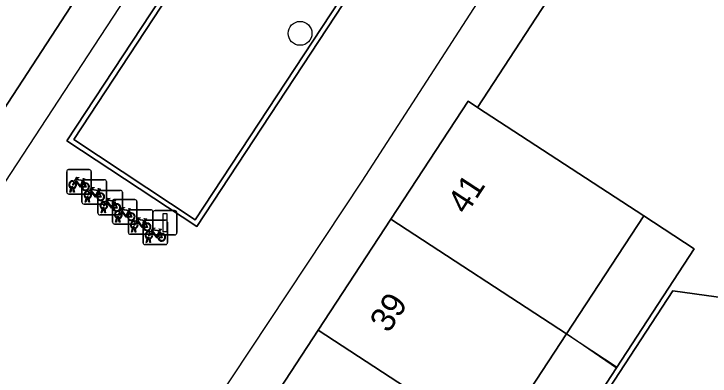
# Model space of a CAD drawing. Extents: x 155640 to 156811, y 382821 to 384049.
# Drawn here: x 156456.82 to 156485.33, y 383747.46 to 383762.3 of the extents above; entities that cross this region are included whole.
import ezdxf

# ---------------------------------------------------------------- set-up
doc = ezdxf.new("R2010")
doc.units = 0
for name, color, linetype in [('IMGEO_Boom', 7, 'Continuous'), ('IMGEO_Fietsenrek', 7, 'Continuous'), ('IMGEO_Lichtmast', 7, 'Continuous'), ('IMGEO_Lijnafwatering', 7, 'Continuous'), ('IMGEO_Muur', 7, 'Continuous'), ('IMGEO_Pand', 7, 'Continuous'), ('IMGEO_Pand_nummerreeks', 7, 'Continuous'), ('IMGEO_Pand_overbouw', 7, 'Continuous'), ('IMGEO_Rijbaan_lokaal_gesloten', 7, 'Continuous'), ('IMGEO_Voetgangersgebied_open', 7, 'Continuous'), ('IMGEO_Voetpad_open', 7, 'Continuous')]:
    doc.layers.add(name, color=color, linetype=linetype)

msp = doc.modelspace()

# ---------------------------------------------------------------- linework, layer by layer
at = {"layer": 'IMGEO_Boom'}
msp.add_circle((156468.536, 383761.508), 0.489, dxfattribs=at)
at = {"layer": 'IMGEO_Fietsenrek'}
for p, q in [((156458.983, 383754.998), (156458.983, 383755.839)), ((156458.983, 383755.839), (156458.983, 383754.998)), ((156459.058, 383755.923), (156459.899, 383755.923)), ((156459.899, 383755.923), (156459.058, 383755.923)), ((156459.983, 383755.848), (156459.983, 383755.007)), ((156459.983, 383755.007), (156459.983, 383755.848)), ((156459.605, 383754.587), (156459.605, 383755.428)), ((156459.605, 383755.428), (156459.605, 383754.587)), ((156459.67, 383755.472), (156459.706, 383755.377)), ((156459.68, 383755.512), (156460.521, 383755.512)), ((156460.521, 383755.512), (156459.68, 383755.512)), ((156460.605, 383755.437), (156460.605, 383754.596)), ((156460.605, 383754.596), (156460.605, 383755.437)), ((156459.11, 383755.007), (156459.149, 383755.167)), ((156459.179, 383755.155), (156459.144, 383755.007)), ((156459.221, 383755.179), (156459.22, 383755.183)), ((156459.262, 383755.007), (156459.228, 383755.149)), ((156459.252, 383755.19), (156459.253, 383755.183)), ((156459.26, 383755.153), (156459.295, 383755.007)), ((156459.908, 383754.923), (156459.067, 383754.923)), ((156459.067, 383754.923), (156459.908, 383754.923)), ((156459.144, 383755.007), (156459.11, 383755.007)), ((156459.295, 383755.007), (156459.262, 383755.007)), ((156460.26, 383754.144), (156460.26, 383754.985)), ((156460.26, 383754.985), (156460.26, 383754.144)), ((156460.292, 383755.061), (156460.328, 383754.966)), ((156460.335, 383755.069), (156461.176, 383755.069)), ((156461.176, 383755.069), (156460.335, 383755.069)), ((156461.26, 383754.994), (156461.26, 383754.153)), ((156461.26, 383754.153), (156461.26, 383754.994)), ((156459.732, 383754.596), (156459.771, 383754.756)), ((156459.766, 383754.596), (156459.732, 383754.596)), ((156459.801, 383754.744), (156459.766, 383754.596)), ((156459.843, 383754.768), (156459.842, 383754.772)), ((156459.884, 383754.596), (156459.85, 383754.738)), ((156459.874, 383754.779), (156459.875, 383754.772)), ((156459.882, 383754.742), (156459.917, 383754.596)), ((156459.917, 383754.596), (156459.884, 383754.596)), ((156460.856, 383753.769), (156460.856, 383754.61)), ((156460.856, 383754.61), (156460.856, 383753.769)), ((156460.931, 383754.694), (156461.772, 383754.694)), ((156461.772, 383754.694), (156460.931, 383754.694)), ((156460.947, 383754.618), (156460.983, 383754.523)), ((156461.856, 383754.619), (156461.856, 383753.778)), ((156461.856, 383753.778), (156461.856, 383754.619)), ((156460.53, 383754.512), (156459.689, 383754.512)), ((156459.689, 383754.512), (156460.53, 383754.512)), ((156460.387, 383754.153), (156460.426, 383754.313)), ((156460.456, 383754.301), (156460.421, 383754.153)), ((156460.498, 383754.325), (156460.497, 383754.329)), ((156460.539, 383754.153), (156460.505, 383754.295)), ((156460.529, 383754.336), (156460.53, 383754.329)), ((156460.537, 383754.299), (156460.572, 383754.153)), ((156461.58, 383754.277), (156462.421, 383754.277)), ((156462.421, 383754.277), (156461.58, 383754.277)), ((156461.185, 383754.069), (156460.344, 383754.069)), ((156460.344, 383754.069), (156461.185, 383754.069)), ((156460.421, 383754.153), (156460.387, 383754.153)), ((156460.572, 383754.153), (156460.539, 383754.153)), ((156461.505, 383753.352), (156461.505, 383754.193)), ((156461.505, 383754.193), (156461.505, 383753.352)), ((156461.543, 383754.243), (156461.579, 383754.148)), ((156462.505, 383754.202), (156462.505, 383753.361)), ((156462.505, 383753.361), (156462.505, 383754.202)), ((156460.983, 383753.778), (156461.022, 383753.938)), ((156461.017, 383753.778), (156460.983, 383753.778)), ((156461.052, 383753.926), (156461.017, 383753.778)), ((156461.094, 383753.95), (156461.093, 383753.954)), ((156461.135, 383753.778), (156461.101, 383753.92)), ((156461.125, 383753.961), (156461.126, 383753.954)), ((156461.133, 383753.924), (156461.168, 383753.778)), ((156461.168, 383753.778), (156461.135, 383753.778)), ((156462.106, 383752.928), (156462.106, 383753.769)), ((156462.106, 383753.769), (156462.106, 383752.928)), ((156462.181, 383753.853), (156463.022, 383753.853)), ((156463.022, 383753.853), (156462.181, 383753.853)), ((156462.192, 383753.826), (156462.228, 383753.731)), ((156463.106, 383753.778), (156463.106, 383752.937)), ((156463.106, 383752.937), (156463.106, 383753.778)), ((156461.781, 383753.694), (156460.94, 383753.694)), ((156460.94, 383753.694), (156461.781, 383753.694)), ((156461.632, 383753.361), (156461.671, 383753.521)), ((156461.701, 383753.509), (156461.666, 383753.361)), ((156461.743, 383753.533), (156461.742, 383753.537)), ((156461.784, 383753.361), (156461.75, 383753.503)), ((156461.774, 383753.544), (156461.775, 383753.537)), ((156461.782, 383753.507), (156461.817, 383753.361)), ((156462.43, 383753.277), (156461.589, 383753.277)), ((156461.589, 383753.277), (156462.43, 383753.277)), ((156461.666, 383753.361), (156461.632, 383753.361)), ((156461.817, 383753.361), (156461.784, 383753.361)), ((156462.793, 383753.402), (156462.829, 383753.307)), ((156463.031, 383752.853), (156462.19, 383752.853)), ((156462.19, 383752.853), (156463.031, 383752.853)), ((156462.233, 383752.937), (156462.272, 383753.097)), ((156462.267, 383752.937), (156462.233, 383752.937)), ((156462.302, 383753.085), (156462.267, 383752.937)), ((156462.344, 383753.109), (156462.343, 383753.113)), ((156462.385, 383752.937), (156462.351, 383753.079)), ((156462.375, 383753.12), (156462.376, 383753.113)), ((156462.383, 383753.083), (156462.418, 383752.937)), ((156462.418, 383752.937), (156462.385, 383752.937))]:
    msp.add_line(p, q, dxfattribs=at)
for points in [[(156459.317, 383755.397), (156459.265, 383755.307), (156459.225, 383755.282), (156459.226, 383755.329), (156459.281, 383755.423)], [(156459.296, 383755.449), (156459.391, 383755.613), (156459.477, 383755.599), (156459.479, 383755.59), (156459.423, 383755.579), (156459.396, 383755.534), (156459.652, 383755.493)], [(156459.592, 383755.205), (156459.542, 383755.205), (156459.351, 383755.456), (156459.332, 383755.424)], [(156459.639, 383755.468), (156459.382, 383755.509), (156459.365, 383755.48), (156459.532, 383755.26), (156459.639, 383755.468)], [(156459.687, 383755.37), (156459.657, 383755.447), (156459.548, 383755.229), (156459.591, 383755.229)], [(156459.652, 383755.493), (156459.677, 383755.542), (156459.671, 383755.546), (156459.648, 383755.55), (156459.636, 383755.557), (156459.635, 383755.56), (156459.637, 383755.565), (156459.732, 383755.55), (156459.734, 383755.54), (156459.724, 383755.527), (156459.712, 383755.521), (156459.698, 383755.527), (156459.67, 383755.472)], [(156459.621, 383755.229), (156459.741, 383755.228), (156459.697, 383755.342)], [(156459.717, 383755.349), (156459.772, 383755.204), (156459.622, 383755.204)], [(156459.918, 383755.038), (156460.013, 383755.202), (156460.099, 383755.188), (156460.101, 383755.179), (156460.045, 383755.168), (156460.018, 383755.123), (156460.274, 383755.082)], [(156460.274, 383755.082), (156460.299, 383755.131), (156460.293, 383755.135), (156460.27, 383755.139), (156460.258, 383755.146), (156460.257, 383755.149), (156460.259, 383755.154), (156460.354, 383755.139), (156460.356, 383755.129), (156460.346, 383755.116), (156460.334, 383755.11), (156460.32, 383755.116), (156460.292, 383755.061)], [(156459.939, 383754.986), (156459.887, 383754.896), (156459.847, 383754.871), (156459.848, 383754.918), (156459.903, 383755.012)], [(156460.214, 383754.794), (156460.164, 383754.794), (156459.973, 383755.045), (156459.954, 383755.013)], [(156460.261, 383755.057), (156460.004, 383755.098), (156459.987, 383755.069), (156460.154, 383754.849), (156460.261, 383755.057)], [(156460.309, 383754.959), (156460.279, 383755.036), (156460.17, 383754.818), (156460.213, 383754.818)], [(156460.243, 383754.818), (156460.363, 383754.817), (156460.319, 383754.931)], [(156460.339, 383754.938), (156460.394, 383754.793), (156460.244, 383754.793)], [(156460.594, 383754.543), (156460.542, 383754.453), (156460.502, 383754.428), (156460.503, 383754.475), (156460.558, 383754.569)], [(156460.573, 383754.595), (156460.668, 383754.759), (156460.754, 383754.745), (156460.756, 383754.736), (156460.7, 383754.725), (156460.673, 383754.68), (156460.929, 383754.639)], [(156460.869, 383754.351), (156460.819, 383754.351), (156460.628, 383754.602), (156460.609, 383754.57)], [(156460.916, 383754.614), (156460.659, 383754.655), (156460.642, 383754.626), (156460.809, 383754.406), (156460.916, 383754.614)], [(156460.964, 383754.516), (156460.934, 383754.593), (156460.825, 383754.375), (156460.868, 383754.375)], [(156460.929, 383754.639), (156460.954, 383754.688), (156460.948, 383754.692), (156460.925, 383754.696), (156460.913, 383754.703), (156460.912, 383754.706), (156460.914, 383754.711), (156461.009, 383754.696), (156461.011, 383754.686), (156461.001, 383754.673), (156460.989, 383754.667), (156460.975, 383754.673), (156460.947, 383754.618)], [(156460.898, 383754.375), (156461.018, 383754.374), (156460.974, 383754.488)], [(156460.994, 383754.495), (156461.049, 383754.35), (156460.899, 383754.35)], [(156461.169, 383754.22), (156461.264, 383754.384), (156461.35, 383754.37), (156461.352, 383754.361), (156461.296, 383754.35), (156461.269, 383754.305), (156461.525, 383754.264)], [(156461.512, 383754.239), (156461.255, 383754.28), (156461.238, 383754.251), (156461.405, 383754.031), (156461.512, 383754.239)], [(156461.525, 383754.264), (156461.55, 383754.313), (156461.544, 383754.317), (156461.521, 383754.321), (156461.509, 383754.328), (156461.508, 383754.331), (156461.51, 383754.336), (156461.605, 383754.321), (156461.607, 383754.311), (156461.597, 383754.298), (156461.585, 383754.292), (156461.571, 383754.298), (156461.543, 383754.243)], [(156461.19, 383754.168), (156461.138, 383754.078), (156461.098, 383754.053), (156461.099, 383754.1), (156461.154, 383754.194)], [(156461.465, 383753.976), (156461.415, 383753.976), (156461.224, 383754.227), (156461.205, 383754.195)], [(156461.56, 383754.141), (156461.53, 383754.218), (156461.421, 383754), (156461.464, 383754)], [(156461.494, 383754), (156461.614, 383753.999), (156461.57, 383754.113)], [(156461.59, 383754.12), (156461.645, 383753.975), (156461.495, 383753.975)], [(156461.839, 383753.751), (156461.787, 383753.661), (156461.747, 383753.636), (156461.748, 383753.683), (156461.803, 383753.777)], [(156461.818, 383753.803), (156461.913, 383753.967), (156461.999, 383753.953), (156462.001, 383753.944), (156461.945, 383753.933), (156461.918, 383753.888), (156462.174, 383753.847)], [(156462.114, 383753.559), (156462.064, 383753.559), (156461.873, 383753.81), (156461.854, 383753.778)], [(156462.161, 383753.822), (156461.904, 383753.863), (156461.887, 383753.834), (156462.054, 383753.614), (156462.161, 383753.822)], [(156462.209, 383753.724), (156462.179, 383753.801), (156462.07, 383753.583), (156462.113, 383753.583)], [(156462.239, 383753.703), (156462.294, 383753.558), (156462.144, 383753.558)], [(156462.174, 383753.847), (156462.199, 383753.896), (156462.193, 383753.9), (156462.17, 383753.904), (156462.158, 383753.911), (156462.157, 383753.914), (156462.159, 383753.919), (156462.254, 383753.904), (156462.256, 383753.894), (156462.246, 383753.881), (156462.234, 383753.875), (156462.22, 383753.881), (156462.192, 383753.826)], [(156462.143, 383753.583), (156462.263, 383753.582), (156462.219, 383753.696)], [(156462.419, 383753.379), (156462.514, 383753.543), (156462.6, 383753.529), (156462.602, 383753.52), (156462.546, 383753.509), (156462.519, 383753.464), (156462.775, 383753.423)], [(156462.762, 383753.398), (156462.505, 383753.439), (156462.488, 383753.41), (156462.655, 383753.19), (156462.762, 383753.398)], [(156462.775, 383753.423), (156462.8, 383753.472), (156462.794, 383753.476), (156462.771, 383753.48), (156462.759, 383753.487), (156462.758, 383753.49), (156462.76, 383753.495), (156462.855, 383753.48), (156462.857, 383753.47), (156462.847, 383753.457), (156462.835, 383753.451), (156462.821, 383753.457), (156462.793, 383753.402)], [(156462.44, 383753.327), (156462.388, 383753.237), (156462.348, 383753.212), (156462.349, 383753.259), (156462.404, 383753.353)], [(156462.715, 383753.135), (156462.665, 383753.135), (156462.474, 383753.386), (156462.455, 383753.354)], [(156462.81, 383753.3), (156462.78, 383753.377), (156462.671, 383753.159), (156462.714, 383753.159)], [(156462.744, 383753.159), (156462.864, 383753.158), (156462.82, 383753.272)], [(156462.84, 383753.279), (156462.895, 383753.134), (156462.745, 383753.134)]]:
    msp.add_lwpolyline(points, dxfattribs=at)
for centre, radius, start, end in [((156459.061, 383755.845), 0.0779, 92.4484, 184.2845), ((156459.061, 383755.845), 0.0779, 92.4484, 184.2845), ((156459.905, 383755.845), 0.0779, 2.4484, 94.2845), ((156459.905, 383755.845), 0.0779, 2.4484, 94.2845), ((156459.223, 383755.308), 0.159, 62.6766, 242.1369), ((156459.223, 383755.308), 0.129, 63.3192, 238.903), ((156459.223, 383755.308), 0.159, 283.5766, 46.6042), ((156459.683, 383755.434), 0.0779, 92.4484, 184.2845), ((156459.683, 383755.434), 0.0779, 92.4484, 184.2845), ((156460.527, 383755.434), 0.0779, 2.4484, 94.2845), ((156460.527, 383755.434), 0.0779, 2.4484, 94.2845), ((156459.203, 383755.179), 0.0499, 12.8025, 158.6934), ((156459.223, 383755.308), 0.159, 253.9967, 271.7867), ((156459.203, 383755.179), 0.0174, 12.8025, 163.4502), ((156459.223, 383755.308), 0.129, 253.415, 269.0204), ((156459.223, 383755.308), 0.129, 283.6043, 43.4302), ((156459.75, 383755.224), 0.159, 113.3408, 178.3217), ((156459.75, 383755.224), 0.159, 187.0065, 105.7708), ((156459.75, 383755.224), 0.129, 113.923, 177.9556), ((156459.75, 383755.224), 0.129, 188.6715, 104.5883), ((156459.061, 383755.001), 0.0779, 182.4484, 274.2845), ((156459.061, 383755.001), 0.0779, 182.4484, 274.2845), ((156459.845, 383754.897), 0.159, 62.6766, 242.1369), ((156459.845, 383754.897), 0.129, 63.3192, 238.903), ((156459.845, 383754.897), 0.129, 283.6043, 43.4302), ((156459.845, 383754.897), 0.159, 283.5766, 46.6042), ((156459.905, 383755.001), 0.0779, 272.4484, 4.2845), ((156459.905, 383755.001), 0.0779, 272.4484, 4.2845), ((156460.372, 383754.813), 0.159, 113.3408, 178.3217), ((156460.372, 383754.813), 0.159, 187.0065, 105.7708), ((156460.372, 383754.813), 0.129, 113.923, 177.9556), ((156460.372, 383754.813), 0.129, 188.6715, 104.5883), ((156460.338, 383754.991), 0.0779, 92.4484, 184.2845), ((156460.338, 383754.991), 0.0779, 92.4484, 184.2845), ((156461.182, 383754.991), 0.0779, 2.4484, 94.2845), ((156461.182, 383754.991), 0.0779, 2.4484, 94.2845), ((156459.683, 383754.59), 0.0779, 182.4484, 274.2845), ((156459.683, 383754.59), 0.0779, 182.4484, 274.2845), ((156459.825, 383754.768), 0.0499, 12.8025, 158.6934), ((156459.845, 383754.897), 0.159, 253.9967, 271.7867), ((156459.825, 383754.768), 0.0174, 12.8025, 163.4502), ((156459.845, 383754.897), 0.129, 253.415, 269.0204), ((156460.5, 383754.454), 0.159, 62.6766, 242.1369), ((156460.5, 383754.454), 0.129, 63.3192, 238.903), ((156460.527, 383754.59), 0.0779, 272.4484, 4.2845), ((156460.527, 383754.59), 0.0779, 272.4484, 4.2845), ((156460.5, 383754.454), 0.159, 283.5766, 46.6042), ((156460.934, 383754.616), 0.0779, 92.4484, 184.2845), ((156460.934, 383754.616), 0.0779, 92.4484, 184.2845), ((156461.778, 383754.616), 0.0779, 2.4484, 94.2845), ((156461.778, 383754.616), 0.0779, 2.4484, 94.2845), ((156460.48, 383754.325), 0.0499, 12.8025, 158.6934), ((156460.5, 383754.454), 0.159, 253.9967, 271.7867), ((156460.48, 383754.325), 0.0174, 12.8025, 163.4502), ((156460.5, 383754.454), 0.129, 253.415, 269.0204), ((156460.5, 383754.454), 0.129, 283.6043, 43.4302), ((156461.027, 383754.37), 0.159, 113.3408, 178.3217), ((156461.027, 383754.37), 0.159, 187.0065, 105.7708), ((156461.027, 383754.37), 0.129, 113.923, 177.9556), ((156461.027, 383754.37), 0.129, 188.6715, 104.5883), ((156461.583, 383754.199), 0.0779, 92.4484, 184.2845), ((156461.583, 383754.199), 0.0779, 92.4484, 184.2845), ((156462.427, 383754.199), 0.0779, 2.4484, 94.2845), ((156462.427, 383754.199), 0.0779, 2.4484, 94.2845), ((156460.338, 383754.147), 0.0779, 182.4484, 274.2845), ((156460.338, 383754.147), 0.0779, 182.4484, 274.2845), ((156461.096, 383754.079), 0.159, 62.6766, 242.1369), ((156461.096, 383754.079), 0.129, 63.3192, 238.903), ((156461.076, 383753.95), 0.0499, 12.8025, 158.6934), ((156461.096, 383754.079), 0.129, 283.6043, 43.4302), ((156461.096, 383754.079), 0.159, 283.5766, 46.6042), ((156461.182, 383754.147), 0.0779, 272.4484, 4.2845), ((156461.182, 383754.147), 0.0779, 272.4484, 4.2845), ((156461.623, 383753.995), 0.159, 113.3408, 178.3217), ((156461.623, 383753.995), 0.159, 187.0065, 105.7708), ((156461.623, 383753.995), 0.129, 113.923, 177.9556), ((156461.623, 383753.995), 0.129, 188.6715, 104.5883), ((156460.934, 383753.772), 0.0779, 182.4484, 274.2845), ((156460.934, 383753.772), 0.0779, 182.4484, 274.2845), ((156461.096, 383754.079), 0.159, 253.9967, 271.7867), ((156461.076, 383753.95), 0.0174, 12.8025, 163.4502), ((156461.096, 383754.079), 0.129, 253.415, 269.0204), ((156461.745, 383753.662), 0.159, 62.6766, 242.1369), ((156461.745, 383753.662), 0.129, 63.3192, 238.903), ((156461.745, 383753.662), 0.129, 283.6043, 43.4302), ((156461.778, 383753.772), 0.0779, 272.4484, 4.2845), ((156461.778, 383753.772), 0.0779, 272.4484, 4.2845), ((156461.745, 383753.662), 0.159, 283.5766, 46.6042), ((156462.184, 383753.775), 0.0779, 92.4484, 184.2845), ((156462.184, 383753.775), 0.0779, 92.4484, 184.2845), ((156462.272, 383753.578), 0.159, 113.3408, 178.3217), ((156462.272, 383753.578), 0.159, 187.0065, 105.7708), ((156462.272, 383753.578), 0.129, 188.6715, 104.5883), ((156463.028, 383753.775), 0.0779, 2.4484, 94.2845), ((156463.028, 383753.775), 0.0779, 2.4484, 94.2845), ((156461.725, 383753.533), 0.0499, 12.8025, 158.6934), ((156461.745, 383753.662), 0.159, 253.9967, 271.7867), ((156461.725, 383753.533), 0.0174, 12.8025, 163.4502), ((156461.745, 383753.662), 0.129, 253.415, 269.0204), ((156462.272, 383753.578), 0.129, 113.923, 177.9556), ((156461.583, 383753.355), 0.0779, 182.4484, 274.2845), ((156461.583, 383753.355), 0.0779, 182.4484, 274.2845), ((156462.346, 383753.238), 0.159, 62.6766, 242.1369), ((156462.346, 383753.238), 0.129, 63.3192, 238.903), ((156462.326, 383753.109), 0.0499, 12.8025, 158.6934), ((156462.326, 383753.109), 0.0174, 12.8025, 163.4502), ((156462.346, 383753.238), 0.129, 283.6043, 43.4302), ((156462.346, 383753.238), 0.159, 283.5766, 46.6042), ((156462.427, 383753.355), 0.0779, 272.4484, 4.2845), ((156462.427, 383753.355), 0.0779, 272.4484, 4.2845), ((156462.873, 383753.154), 0.159, 113.3408, 178.3217), ((156462.873, 383753.154), 0.159, 187.0065, 105.7708), ((156462.873, 383753.154), 0.129, 113.923, 177.9556), ((156462.873, 383753.154), 0.129, 188.6715, 104.5883), ((156462.184, 383752.931), 0.0779, 182.4484, 274.2845), ((156462.184, 383752.931), 0.0779, 182.4484, 274.2845), ((156462.346, 383753.238), 0.159, 253.9967, 271.7867), ((156462.346, 383753.238), 0.129, 253.415, 269.0204), ((156463.028, 383752.931), 0.0779, 272.4484, 4.2845), ((156463.028, 383752.931), 0.0779, 272.4484, 4.2845)]:
    msp.add_arc(centre, radius, start, end, dxfattribs=at)
at = {"layer": 'IMGEO_Lichtmast'}
for p, q in [((156462.505, 383753.347), (156462.505, 383754.147)), ((156462.505, 383754.147), (156462.505, 383753.347)), ((156462.605, 383754.247), (156463.395, 383754.247)), ((156463.395, 383754.247), (156462.605, 383754.247)), ((156463.495, 383754.147), (156463.495, 383753.347)), ((156463.495, 383753.347), (156463.495, 383754.147)), ((156463.395, 383753.247), (156462.605, 383753.247)), ((156462.605, 383753.247), (156463.395, 383753.247))]:
    msp.add_line(p, q, dxfattribs=at)
msp.add_lwpolyline([(156462.925, 383754.122), (156463.075, 383754.122), (156463.075, 383753.372), (156462.925, 383753.372), (156462.925, 383754.122)], dxfattribs=at)
for centre, start, end in [((156462.605, 383754.147), 90, 180), ((156462.605, 383754.147), 90, 180), ((156463.395, 383754.147), 0, 90), ((156463.395, 383754.147), 360, 90), ((156462.605, 383753.347), 180, 270), ((156462.605, 383753.347), 180, 270), ((156463.395, 383753.347), 270, 0), ((156463.395, 383753.347), 270, 0)]:
    msp.add_arc(centre, 0.1, start, end, dxfattribs=at)
at = {"layer": 'IMGEO_Lijnafwatering'}
for points in [[(156472.253, 383779.565), (156460.088, 383760.982)], [(156481.391, 383771.435), (156471.067, 383755.451)], [(156460.088, 383760.982), (156447.726, 383742.098)], [(156471.067, 383755.451), (156459.635, 383738.197)]]:
    msp.add_lwpolyline(points, dxfattribs=at)
at = {"layer": 'IMGEO_Muur'}
msp.add_lwpolyline([(156483.001, 383769.51), (156475.806, 383758.471)], dxfattribs=at)
for points in [[(156472.306, 383765.783), (156466.993, 383769.287), (156458.99, 383757.098), (156464.303, 383753.596)], [(156459.267, 383757.155), (156467.05, 383769.009), (156472.029, 383765.726), (156464.246, 383753.873)]]:
    msp.add_lwpolyline(points, close=True, dxfattribs=at)
at = {"layer": 'IMGEO_Pand'}
for points in [[(156448.065, 383769.871), (156445.081, 383765.315), (156456.167, 383758.053), (156459.148, 383762.611)], [(156482.61, 383754.028), (156475.806, 383758.471), (156475.417, 383758.73), (156472.251, 383753.89), (156479.445, 383749.193)], [(156479.445, 383749.193), (156472.251, 383753.89), (156469.274, 383749.341), (156476.467, 383744.644)], [(156476.467, 383744.644), (156469.274, 383749.341), (156466.337, 383744.851), (156473.528, 383740.155)]]:
    msp.add_lwpolyline(points, close=True, dxfattribs=at)
msp.add_lwpolyline([(156526.125, 383742.921), (156504.403, 383768.001), (156496.961, 383761.545), (156495.141, 383758.761), (156489.522, 383750.169), (156483.796, 383750.953), (156467.607, 383726.148), (156463.541, 383696.89), (156450.981, 383698.723), (156451.111, 383699.61), (156451.369, 383699.433), (156453.11, 383701.958), (156448.797, 383704.86), (156447.156, 383702.372), (156442.019, 383705.761), (156438.461, 383700.239), (156438.115, 383699.703), (156438.014, 383699.718), (156436.208, 383686.52)], dxfattribs=at)
at = {"layer": 'IMGEO_Pand_overbouw'}
for points in [[(156482.61, 383754.028), (156479.445, 383749.193), (156481.523, 383747.836), (156484.681, 383752.675)], [(156479.445, 383749.193), (156476.467, 383744.644), (156478.551, 383743.283), (156481.501, 383747.785)]]:
    msp.add_lwpolyline(points, close=True, dxfattribs=at)
at = {"layer": 'IMGEO_Rijbaan_lokaal_gesloten'}
msp.add_lwpolyline([(156464.246, 383753.873), (156472.029, 383765.726), (156467.05, 383769.009), (156459.267, 383757.155)], close=True, dxfattribs=at)
at = {"layer": 'IMGEO_Voetgangersgebied_open'}
msp.add_lwpolyline([(156466.337, 383744.851), (156469.274, 383749.341), (156472.251, 383753.89), (156475.417, 383758.73), (156475.806, 383758.471), (156483.001, 383769.51), (156481.391, 383771.435), (156477.589, 383775.981), (156471.098, 383780.883), (156468.09, 383776.284), (156465.11, 383771.726), (156462.129, 383767.169), (156459.148, 383762.611), (156456.167, 383758.053), (156453.187, 383753.496), (156450.206, 383748.938), (156447.225, 383744.38)], dxfattribs=at)
msp.add_lwpolyline([(156464.303, 383753.596), (156458.99, 383757.098), (156466.993, 383769.287), (156472.306, 383765.783)], close=True, dxfattribs=at)
at = {"layer": 'IMGEO_Voetpad_open'}
for points in [[(156443.341, 383707.811), (156442.019, 383705.761), (156447.156, 383702.372), (156448.797, 383704.86), (156453.11, 383701.958), (156451.369, 383699.433), (156451.111, 383699.61), (156450.981, 383698.723), (156463.541, 383696.89), (156467.607, 383726.148), (156483.796, 383750.953), (156489.522, 383750.169), (156495.141, 383758.761), (156491.34, 383763.141), (156484.606, 383770.903), (156483.001, 383769.51), (156475.806, 383758.471), (156482.61, 383754.028), (156484.681, 383752.675), (156454.756, 383706.822), (156452.619, 383708.217), (156445.881, 383712.618), (156442.937, 383708.11)], [(156452.619, 383708.217), (156454.756, 383706.822), (156484.681, 383752.675), (156482.61, 383754.028), (156479.445, 383749.193), (156476.467, 383744.644), (156473.528, 383740.155), (156470.565, 383735.629), (156467.606, 383731.11), (156464.65, 383726.595), (156461.689, 383722.072), (156458.727, 383717.547), (156455.766, 383713.025)]]:
    msp.add_lwpolyline(points, close=True, dxfattribs=at)

# ---------------------------------------------------------------- texts
at = {"layer": 'IMGEO_Pand_nummerreeks'}
for s, rotation, p in [('41', 56.8088, (156475.34, 383754.045)), ('39', 56.7973, (156472.163, 383749.191))]:
    msp.add_text(s, height=1, rotation=rotation, dxfattribs=at).set_placement(p)

doc.saveas('drawing.dxf')
